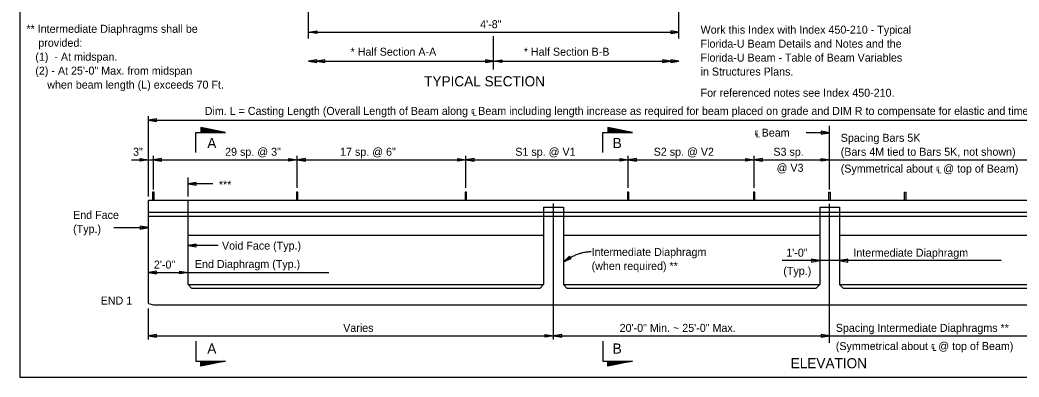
# Model space of a CAD drawing. Extents: x 120735 to 120771, y 120670.1 to 120685.4.
# Drawn here: x 120734.99 to 120747.58, y 120671.41 to 120675.91 of the extents above; entities that cross this region are included whole.
import ezdxf

# ---------------------------------------------------------------- set-up
doc = ezdxf.new("R2010")
doc.units = 0
for name, color, linetype in [('ActivePts-ConstElements', 7, 'Continuous'), ('BeamConc', 7, 'Continuous'), ('BeamConc_h', 7, 'Continuous'), ('CL_Major', 7, 'Continuous'), ('Dimension', 7, 'Continuous'), ('Rebar', 7, 'Continuous'), ('TextStructures', 7, 'Continuous')]:
    doc.layers.add(name, color=color, linetype=linetype)

# ---------------------------------------------------------------- blocks, each defined once
blk = doc.blocks.new('ALT')
at = {"layer": 'Dimension'}
for points in [[(0, 0), (-0.00041, -0.000069), (-0.00041, 0.000069)], [(-0.000121, 0), (-0.000397, -0.000043), (-0.000397, 0.000043)], [(-0.000233, 0), (-0.000374, -0.000023), (-0.000374, 0.000023)]]:
    blk.add_lwpolyline(points, close=True, dxfattribs=at)

msp = doc.modelspace()

# ---------------------------------------------------------------- linework, layer by layer
at = {"layer": 'ActivePts-ConstElements'}
msp.add_lwpolyline([(120734.992, 120671.407), (120755.517, 120671.407), (120755.517, 120684.38), (120734.992, 120684.38)], close=True, dxfattribs=at)
at = {"layer": 'BeamConc'}
for p, q in [((120736.609, 120672.335), (120736.609, 120673.632)), ((120754.144, 120673.632), (120736.609, 120673.632)), ((120736.609, 120673.486), (120754.144, 120673.486)), ((120736.609, 120673.436), (120754.144, 120673.436)), ((120736.609, 120672.335), (120736.672, 120672.319)), ((120736.672, 120672.319), (120754.082, 120672.319))]:
    msp.add_line(p, q, dxfattribs=at)
at = {"layer": 'BeamConc_h'}
for p, q in [((120737.109, 120672.572), (120737.109, 120673.632)), ((120741.587, 120673.548), (120741.837, 120673.548)), ((120741.587, 120673.548), (120741.587, 120672.572)), ((120741.837, 120673.548), (120741.837, 120672.572)), ((120745.065, 120673.548), (120745.315, 120673.548)), ((120745.065, 120673.548), (120745.065, 120672.572)), ((120745.315, 120673.548), (120745.315, 120672.572)), ((120737.109, 120673.194), (120741.587, 120673.194)), ((120741.837, 120673.194), (120745.065, 120673.194)), ((120745.315, 120673.194), (120748.542, 120673.194)), ((120737.153, 120672.528), (120737.109, 120672.572)), ((120737.109, 120672.572), (120741.587, 120672.572)), ((120737.153, 120672.528), (120741.543, 120672.528)), ((120741.543, 120672.528), (120741.587, 120672.572)), ((120741.837, 120672.572), (120745.065, 120672.572)), ((120741.882, 120672.528), (120741.837, 120672.572)), ((120741.882, 120672.528), (120745.02, 120672.528)), ((120745.02, 120672.528), (120745.065, 120672.572)), ((120745.315, 120672.572), (120748.542, 120672.572)), ((120745.359, 120672.528), (120745.315, 120672.572)), ((120745.359, 120672.528), (120748.497, 120672.528))]:
    msp.add_line(p, q, dxfattribs=at)
at = {"layer": 'CL_Major'}
for p, q in [((120740.958, 120675.285), (120740.958, 120675.704)), ((120745.19, 120673.772), (120745.19, 120674.575)), ((120741.712, 120671.878), (120741.712, 120673.594)), ((120745.19, 120671.838), (120745.19, 120673.589))]:
    msp.add_line(p, q, dxfattribs=at)
at = {"layer": 'Dimension'}
for p, q in [((120738.625, 120675.673), (120738.625, 120676.03)), ((120743.292, 120675.673), (120743.292, 120676.03)), ((120738.625, 120675.754), (120743.292, 120675.754)), ((120738.625, 120675.387), (120743.292, 120675.387)), ((120736.609, 120673.682), (120736.609, 120674.696)), ((120736.609, 120674.646), (120754.144, 120674.646)), ((120737.581, 120674.489), (120737.268, 120674.544)), ((120737.268, 120674.537), (120737.581, 120674.489)), ((120737.581, 120674.489), (120737.268, 120674.529)), ((120737.268, 120674.519), (120737.581, 120674.489)), ((120737.581, 120674.489), (120737.268, 120674.51)), ((120737.268, 120674.5), (120737.581, 120674.489)), ((120742.709, 120674.489), (120742.397, 120674.544)), ((120742.397, 120674.537), (120742.709, 120674.489)), ((120742.709, 120674.489), (120742.397, 120674.529)), ((120742.397, 120674.519), (120742.709, 120674.489)), ((120742.709, 120674.489), (120742.397, 120674.51)), ((120742.397, 120674.5), (120742.709, 120674.489)), ((120745.19, 120674.486), (120744.893, 120674.486)), ((120736.395, 120674.146), (120748.408, 120674.146)), ((120736.672, 120673.769), (120736.672, 120674.196)), ((120738.484, 120673.79), (120738.484, 120674.196)), ((120740.609, 120673.79), (120740.609, 120674.196)), ((120742.654, 120673.79), (120742.654, 120674.196)), ((120744.239, 120673.79), (120744.239, 120674.196)), ((120737.109, 120673.683), (120737.109, 120673.923)), ((120737.422, 120673.843), (120737.109, 120673.843)), ((120736.176, 120673.29), (120736.609, 120673.29)), ((120737.489, 120673.066), (120737.109, 120673.066)), ((120747.35, 120672.874), (120744.593, 120672.874)), ((120736.609, 120672.724), (120738.881, 120672.724)), ((120736.609, 120671.878), (120736.609, 120672.272)), ((120736.609, 120671.926), (120748.276, 120671.926)), ((120737.268, 120671.595), (120737.581, 120671.607)), ((120737.581, 120671.607), (120737.268, 120671.585)), ((120737.268, 120671.576), (120737.581, 120671.607)), ((120737.581, 120671.607), (120737.268, 120671.567)), ((120737.268, 120671.559), (120737.581, 120671.607)), ((120737.581, 120671.607), (120737.268, 120671.552)), ((120742.397, 120671.595), (120742.709, 120671.607)), ((120742.709, 120671.607), (120742.397, 120671.585)), ((120742.397, 120671.576), (120742.709, 120671.607)), ((120742.709, 120671.607), (120742.397, 120671.567)), ((120742.397, 120671.559), (120742.709, 120671.607)), ((120742.709, 120671.607), (120742.397, 120671.552))]:
    msp.add_line(p, q, dxfattribs=at)
for points in [[(120743.292, 120675.754), (120743.188, 120675.771), (120743.188, 120675.736)], [(120738.625, 120675.387), (120738.729, 120675.37), (120738.729, 120675.405)], [(120738.729, 120675.387), (120738.833, 120675.37), (120738.833, 120675.405)], [(120740.958, 120675.387), (120740.854, 120675.405), (120740.854, 120675.37)], [(120740.958, 120675.387), (120741.063, 120675.405), (120741.063, 120675.37)], [(120743.188, 120675.387), (120743.084, 120675.405), (120743.084, 120675.37)], [(120743.292, 120675.387), (120743.188, 120675.405), (120743.188, 120675.37)], [(120736.609, 120674.646), (120736.713, 120674.628), (120736.713, 120674.663)], [(120745.19, 120674.486), (120745.085, 120674.504), (120745.085, 120674.469)], [(120736.609, 120674.146), (120736.505, 120674.128), (120736.505, 120674.163)], [(120736.672, 120674.146), (120736.776, 120674.128), (120736.776, 120674.163)], [(120738.484, 120674.146), (120738.38, 120674.128), (120738.38, 120674.163)], [(120738.484, 120674.146), (120738.588, 120674.128), (120738.588, 120674.163)], [(120740.609, 120674.146), (120740.505, 120674.128), (120740.505, 120674.163)], [(120740.609, 120674.146), (120740.713, 120674.128), (120740.713, 120674.163)], [(120742.654, 120674.146), (120742.55, 120674.128), (120742.55, 120674.163)], [(120742.654, 120674.146), (120742.758, 120674.128), (120742.758, 120674.163)], [(120744.239, 120674.146), (120744.134, 120674.128), (120744.134, 120674.163)], [(120744.239, 120674.146), (120744.343, 120674.128), (120744.343, 120674.163)], [(120745.19, 120674.146), (120745.085, 120674.128), (120745.085, 120674.163)], [(120737.109, 120673.843), (120737.213, 120673.825), (120737.213, 120673.86)], [(120736.609, 120673.29), (120736.505, 120673.308), (120736.505, 120673.272)], [(120737.109, 120673.066), (120737.213, 120673.048), (120737.213, 120673.083)], [(120741.838, 120672.857), (120741.933, 120672.903), (120741.913, 120672.932)], [(120745.065, 120672.874), (120744.96, 120672.891), (120744.96, 120672.856)], [(120745.315, 120672.874), (120745.419, 120672.856), (120745.419, 120672.891)], [(120736.609, 120672.724), (120736.713, 120672.706), (120736.713, 120672.742)], [(120737.109, 120672.724), (120737.005, 120672.706), (120737.005, 120672.742)], [(120736.609, 120671.926), (120736.713, 120671.908), (120736.713, 120671.943)], [(120741.712, 120671.926), (120741.608, 120671.908), (120741.608, 120671.943)], [(120741.713, 120671.926), (120741.817, 120671.908), (120741.817, 120671.943)], [(120745.19, 120671.926), (120745.085, 120671.943), (120745.085, 120671.908)]]:
    msp.add_lwpolyline(points, close=True, dxfattribs=at)
for points in [[(120737.206, 120674.239), (120737.206, 120674.489), (120737.581, 120674.489), (120737.268, 120674.551), (120737.268, 120674.489)], [(120742.334, 120674.239), (120742.334, 120674.489), (120742.709, 120674.489), (120742.397, 120674.551), (120742.397, 120674.489)], [(120737.206, 120671.857), (120737.206, 120671.607), (120737.581, 120671.607), (120737.268, 120671.544), (120737.268, 120671.607)], [(120742.334, 120671.857), (120742.334, 120671.607), (120742.709, 120671.607), (120742.397, 120671.544), (120742.397, 120671.607)]]:
    msp.add_lwpolyline(points, dxfattribs=at)
msp.add_open_spline([(120742.185, 120672.984), (120742.016, 120672.984), (120741.838, 120672.857)], degree=2, dxfattribs=at)
at = {"layer": 'Rebar'}
for p, q in [((120736.68, 120673.739), (120736.663, 120673.739)), ((120736.663, 120673.739), (120736.663, 120673.632)), ((120736.68, 120673.632), (120736.68, 120673.739)), ((120738.493, 120673.739), (120738.475, 120673.739)), ((120738.475, 120673.739), (120738.475, 120673.632)), ((120738.493, 120673.632), (120738.493, 120673.739)), ((120740.618, 120673.739), (120740.6, 120673.739)), ((120740.6, 120673.739), (120740.6, 120673.632)), ((120740.618, 120673.632), (120740.618, 120673.739)), ((120742.662, 120673.739), (120742.645, 120673.739)), ((120742.645, 120673.739), (120742.645, 120673.632)), ((120742.662, 120673.632), (120742.662, 120673.739)), ((120744.247, 120673.739), (120744.23, 120673.739)), ((120744.23, 120673.739), (120744.23, 120673.632)), ((120744.247, 120673.632), (120744.247, 120673.739)), ((120745.181, 120673.632), (120745.181, 120673.739)), ((120745.181, 120673.739), (120745.198, 120673.739)), ((120745.198, 120673.739), (120745.198, 120673.632)), ((120746.132, 120673.632), (120746.132, 120673.739)), ((120746.132, 120673.739), (120746.149, 120673.739)), ((120746.149, 120673.739), (120746.149, 120673.632))]:
    msp.add_line(p, q, dxfattribs=at)

# ---------------------------------------------------------------- block references
at = {"layer": 'Dimension', "xscale": 254, "yscale": 255.88988095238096, "rotation": 180}
msp.add_blockref('ALT', (120738.625, 120675.754), dxfattribs=at)
msp.add_blockref('ALT', (120738.625, 120675.754), dxfattribs=at)
at = {"layer": 'Dimension', "xscale": 164.50777202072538, "yscale": 167.927734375}
msp.add_blockref('ALT', (120745.19, 120674.145), dxfattribs=at)
msp.add_blockref('ALT', (120745.19, 120674.145), dxfattribs=at)

# ---------------------------------------------------------------- texts
at = {"layer": 'Dimension'}
for s, p in [('** Intermediate Diaphragms shall be', (120735.073, 120675.746)), ('  Work this Index with Index 450-210 - Typical', (120743.49, 120675.735)), ('    provided:', (120735.073, 120675.57)), ('  Florida-U Beam Details and Notes and the', (120743.49, 120675.559)), ('   (1)  - At midspan.', (120735.073, 120675.394)), ('  Florida-U Beam - Table of Beam Variables', (120743.49, 120675.383)), ('   (2) - At 25\'-0" Max. from midspan', (120735.073, 120675.218)), ('  in Structures Plans.', (120743.49, 120675.207)), ('       when beam length (L) exceeds 70 Ft.', (120735.073, 120675.042)), ('Spacing Bars 5K', (120745.33, 120674.372)), ('(Bars 4M tied to Bars 5K, not shown)', (120745.33, 120674.196)), ('End Face', (120735.661, 120673.4)), ('(Typ.)', (120735.661, 120673.224)), ('Intermediate Diaphragm ', (120742.192, 120672.933)), ('(when required) **', (120742.192, 120672.757))]:
    msp.add_text(s, height=0.1008, dxfattribs=at).set_placement(p)
at = {"layer": 'TextStructures'}
for s, height, p in [('4\'-8"', 0.1008, (120740.788, 120675.804)), ('* Half Section A-A', 0.1008, (120739.156, 120675.457)), ('* Half Section B-B', 0.1008, (120741.338, 120675.457)), ('TYPICAL SECTION', 0.128, (120740.083, 120675.071)), ('  For referenced notes see Index 450-210.', 0.1008, (120743.49, 120674.94)), ('Dim. L = Casting Length (Overall Length of Beam along ℄ Beam including length increase as required for beam placed on grade and DIM R to compensate for elastic and time dependent shortening effects)', 0.1008, (120737.319, 120674.711)), ('℄ Beam', 0.1008, (120744.242, 120674.437)), ('A', 0.128, (120737.351, 120674.292)), ('B', 0.128, (120742.457, 120674.292)), ('3"', 0.1008, (120736.416, 120674.196)), ('29 sp. @ 3"', 0.1008, (120737.576, 120674.196)), ('17 sp. @ 6"', 0.1008, (120739.024, 120674.196)), ('S1 sp. @ V1', 0.1008, (120741.231, 120674.196)), ('S2 sp. @ V2', 0.1008, (120742.974, 120674.196)), ('S3 sp.', 0.1008, (120744.482, 120674.196)), ('@ V3', 0.1008, (120744.522, 120673.994)), ('(Symmetrical about ℄ @ top of Beam)', 0.1008, (120745.33, 120673.984)), ('***', 0.1008, (120737.497, 120673.783)), ('Void Face (Typ.)', 0.1008, (120737.536, 120673.013)), ('1\'-0"', 0.1008, (120744.644, 120672.924)), ('Intermediate Diaphragm ', 0.1008, (120745.489, 120672.924)), ('2\'-0"', 0.1008, (120736.679, 120672.774)), ('End Diaphragm (Typ.)', 0.1008, (120737.195, 120672.781)), ('(Typ.)', 0.1008, (120744.607, 120672.695)), ('END 1', 0.1008, (120736.008, 120672.32)), ('Varies ', 0.1008, (120739.063, 120671.976)), ('20\'-0" Min. ~ 25\'-0" Max. ', 0.1008, (120742.545, 120671.976)), ('Spacing Intermediate Diaphragms **', 0.1008, (120745.268, 120671.976)), ('A', 0.128, (120737.351, 120671.702)), ('B', 0.128, (120742.457, 120671.702)), ('(Symmetrical about ℄ @ top of Beam)', 0.1008, (120745.268, 120671.747)), ('ELEVATION', 0.128, (120744.7, 120671.517))]:
    msp.add_text(s, height=height, dxfattribs=at).set_placement(p)

doc.saveas('drawing.dxf')
